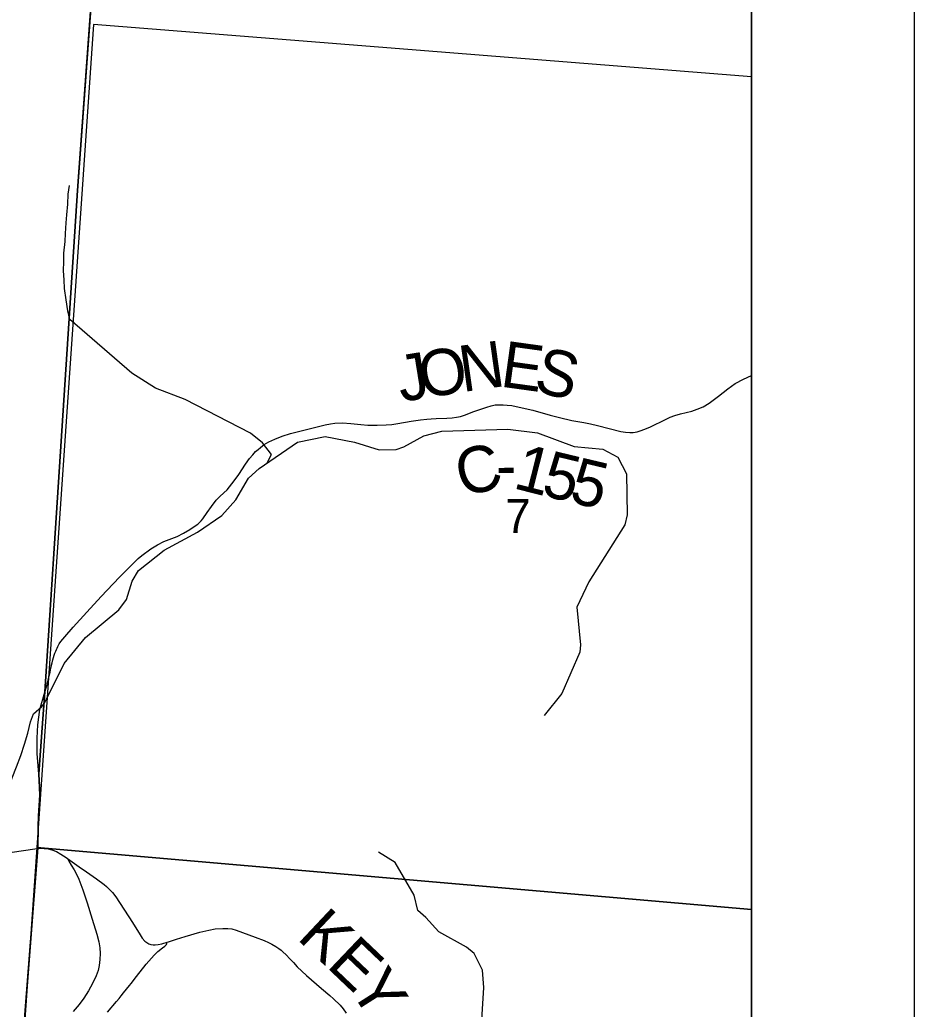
# Model space of a CAD drawing. Extents: x 0 to 42, y 0 to 22.
# Drawn here: x 8.45 to 9, y 18.928 to 19.536 of the extents above; entities that cross this region are included whole.
import ezdxf

# ---------------------------------------------------------------- set-up
doc = ezdxf.new("R2010")
doc.units = 0
for name, color, linetype in [('GM_X_County_Road', 7, 'Continuous'), ('GM_X_County_Road_Text', 7, 'Continuous'), ('GM_X_Minor_River', 7, 'Continuous'), ('GM_X_Section_Text', 7, 'Continuous'), ('GM_X_Township', 7, 'Continuous'), ('GM_X_Township_Road', 7, 'Continuous'), ('GM_X_Unincorporated', 7, 'Continuous'), ('SH_Cut_Line', 7, 'Continuous'), ('SH_Data', 7, 'Continuous')]:
    doc.layers.add(name, color=color, linetype=linetype)

msp = doc.modelspace()

# ---------------------------------------------------------------- linework, layer by layer
at = {"layer": 'GM_X_County_Road'}
for points in [[(8.46528, 19.12263), (8.46663, 19.12748), (8.46798, 19.13277), (8.46844, 19.13497), (8.46903, 19.13775), (8.46976, 19.14081), (8.47023, 19.14271), (8.47061, 19.1441), (8.47102, 19.14549), (8.47149, 19.14679), (8.47194, 19.14792), (8.47238, 19.14897), (8.47279, 19.14985), (8.47331, 19.15089), (8.47413, 19.1524), (8.4751, 19.15389), (8.47761, 19.15684), (8.48271, 19.16262), (8.49117, 19.17183), (8.4999, 19.18152), (8.50353, 19.18538), (8.51114, 19.1934), (8.51525, 19.19755), (8.51948, 19.20165), (8.52275, 19.20496), (8.52494, 19.20688), (8.53036, 19.2109), (8.53459, 19.21341), (8.53849, 19.21537), (8.54659, 19.2184), (8.55058, 19.22047), (8.55448, 19.22282), (8.55775, 19.22498), (8.55931, 19.22613), (8.56039, 19.22709), (8.56146, 19.22821), (8.56246, 19.2294), (8.56513, 19.23319), (8.56776, 19.23698), (8.57071, 19.24077), (8.57287, 19.24304), (8.57542, 19.24535), (8.57737, 19.24723), (8.58168, 19.25265), (8.58459, 19.25664), (8.58865, 19.26293), (8.5912, 19.26645), (8.59312, 19.2688), (8.59483, 19.27067), (8.59643, 19.27207), (8.59786, 19.2733), (8.6001, 19.27498), (8.60313, 19.27673), (8.60663, 19.27844), (8.61118, 19.28024), (8.61644, 19.28183), (8.63108, 19.28562), (8.63777, 19.28718), (8.64092, 19.28778), (8.64371, 19.28812), (8.64833, 19.28833), (8.6534, 19.28805), (8.65958, 19.28738), (8.66397, 19.28702), (8.66963, 19.28694), (8.67517, 19.2871), (8.67864, 19.28746), (8.68243, 19.28802), (8.69052, 19.28937), (8.69627, 19.29025), (8.70017, 19.29073), (8.70296, 19.29096), (8.70588, 19.29109), (8.71247, 19.29135), (8.71579, 19.29157), (8.71843, 19.29184), (8.72095, 19.29228), (8.72402, 19.29328), (8.72844, 19.29507), (8.73339, 19.2969), (8.73705, 19.2981), (8.73981, 19.29886), (8.74232, 19.29942), (8.74475, 19.29954), (8.74722, 19.29954), (8.74961, 19.29934), (8.75244, 19.29898), (8.7552, 19.29846), (8.76532, 19.29619), (8.77601, 19.29316), (8.78191, 19.2916), (8.78937, 19.28984), (8.7967, 19.28853), (8.80097, 19.28771), (8.80523, 19.28666), (8.81959, 19.28303), (8.82246, 19.28263), (8.82509, 19.28239), (8.82704, 19.28247), (8.82844, 19.28259), (8.82963, 19.28283), (8.83139, 19.28339), (8.83426, 19.28442), (8.83777, 19.2859), (8.84694, 19.29045), (8.84985, 19.29184), (8.85284, 19.29292), (8.85619, 19.29396), (8.86317, 19.29563), (8.86656, 19.29675), (8.8701, 19.29818), (8.87389, 19.30042), (8.87957, 19.30472), (8.88526, 19.30938), (8.88988, 19.31254), (8.89498, 19.31521), (8.9, 19.3175)], [(8.46096, 19.02669), (8.46128, 19.03985), (8.4615, 19.04636), (8.4622, 19.05908), (8.46218, 19.06373), (8.46163, 19.07227)], [(8.43815, 19.02336), (8.45911, 19.02642), (8.46096, 19.02669)], [(8.46096, 19.02669), (8.46322, 19.02669), (8.46477, 19.02662), (8.46733, 19.02626), (8.46952, 19.0257), (8.47236, 19.02465), (8.47502, 19.02314), (8.47831, 19.02094), (8.47911, 19.02037), (8.48635, 19.01523), (8.49092, 19.01212), (8.49699, 19.00795), (8.5017, 19.0045), (8.50322, 19.0032), (8.50472, 19.00182), (8.50686, 18.9995), (8.50888, 18.99685), (8.51923, 18.9811), (8.52385, 18.9735), (8.52518, 18.97136), (8.52674, 18.96951), (8.52801, 18.96864), (8.52923, 18.96801), (8.5305, 18.96754), (8.53183, 18.96731), (8.53316, 18.96731), (8.53501, 18.96754), (8.5372, 18.96801), (8.5406, 18.969), (8.54136, 18.96922), (8.54616, 18.97072), (8.55153, 18.97252), (8.56069, 18.9751), (8.56604, 18.97639), (8.57008, 18.97708), (8.57477, 18.97737), (8.57783, 18.97743), (8.58032, 18.97708), (8.58286, 18.97639), (8.59465, 18.97205), (8.6002, 18.96986), (8.60285, 18.96864), (8.60483, 18.96765), (8.60725, 18.96627), (8.60909, 18.96506), (8.61054, 18.96396), (8.61172, 18.96291), (8.61372, 18.96113), (8.61597, 18.95876), (8.61817, 18.95633), (8.62048, 18.95379), (8.62331, 18.95113), (8.62626, 18.94853), (8.63533, 18.94033), (8.64054, 18.93605), (8.64285, 18.93402), (8.64683, 18.93015), (8.64874, 18.9279), (8.6507, 18.9253)]]:
    msp.add_lwpolyline(points, dxfattribs=at)
at = {"layer": 'GM_X_Minor_River'}
for points in [[(8.48061, 19.35197), (8.47947, 19.35733), (8.47836, 19.36397), (8.47743, 19.37099), (8.47707, 19.3763), (8.47671, 19.38198), (8.47692, 19.38767), (8.47693, 19.39279), (8.47771, 19.39999), (8.47792, 19.40492), (8.47832, 19.41136), (8.47871, 19.41629), (8.4793, 19.42292), (8.4797, 19.42898), (8.48047, 19.43448)], [(8.60206, 19.2637), (8.60476, 19.26899), (8.59916, 19.27608), (8.59183, 19.28205), (8.55164, 19.30267), (8.53331, 19.30973), (8.5188, 19.31902), (8.48061, 19.35197)], [(8.46515, 19.11605), (8.47705, 19.14032), (8.49027, 19.15628), (8.51068, 19.17338), (8.51541, 19.17965), (8.51899, 19.19104), (8.52295, 19.19749), (8.53864, 19.21004), (8.55906, 19.22108), (8.57418, 19.23135), (8.58268, 19.24104), (8.59043, 19.25433), (8.59704, 19.26023), (8.62067, 19.27658), (8.63769, 19.28003), (8.65567, 19.27646), (8.67081, 19.27175), (8.6814, 19.27196), (8.68613, 19.27367), (8.69842, 19.28033), (8.70939, 19.2832), (8.75006, 19.28441), (8.76823, 19.28217), (8.79075, 19.27387), (8.80854, 19.2722), (8.81762, 19.26728), (8.82312, 19.25705), (8.82334, 19.23183), (8.82202, 19.22557), (8.79993, 19.19063), (8.79257, 19.17506), (8.79467, 19.15193), (8.7943, 19.14737), (8.78317, 19.12194), (8.7724, 19.10845)], [(8.42381, 18.98866), (8.4272, 18.98918), (8.43346, 18.99106), (8.43613, 18.99807), (8.43653, 19.00413), (8.43541, 19.00925), (8.43202, 19.01533), (8.43015, 19.02197), (8.43092, 19.02841), (8.43473, 19.03503), (8.43721, 19.04185), (8.43818, 19.04734), (8.43933, 19.05246), (8.44086, 19.05814), (8.44296, 19.06325), (8.44525, 19.07007), (8.44792, 19.07689), (8.4504, 19.0837), (8.4527, 19.09071), (8.4548, 19.09753), (8.45653, 19.10454), (8.45825, 19.10946), (8.46337, 19.11381), (8.46515, 19.11605)], [(8.74207, 18.82694), (8.73315, 18.85423), (8.72649, 18.88646), (8.72724, 18.89159), (8.73309, 18.90468), (8.73532, 18.9411), (8.73455, 18.95172), (8.72924, 18.96195), (8.7247, 18.96593), (8.70766, 18.97519), (8.6997, 18.98409), (8.69478, 18.98844), (8.6925, 18.99792), (8.68075, 19.018), (8.67052, 19.02424)]]:
    msp.add_lwpolyline(points, dxfattribs=at)
at = {"layer": 'GM_X_Township'}
msp.add_lwpolyline([(8.5294, 20.03351), (8.48531, 19.43126), (8.46517, 19.12289), (8.46366, 19.1008), (8.46152, 19.07253), (8.46207, 19.06399), (8.4621, 19.05934), (8.4614, 19.04662), (8.46117, 19.04011), (8.46085, 19.02695), (8.42127, 18.51405), (8.38769, 18.10646)], dxfattribs=at)
at = {"layer": 'GM_X_Township_Road'}
msp.add_lwpolyline([(8.9, 16.95771), (8.9, 20.00639), (8.75955, 20.01746), (8.65628, 20.02413), (8.5294, 20.03351), (8.48531, 19.43126), (8.46517, 19.12289), (8.46366, 19.1008), (8.46152, 19.07253), (8.46207, 19.06399), (8.4621, 19.05934), (8.4614, 19.04662), (8.46117, 19.04011), (8.46085, 19.02695), (8.42127, 18.51405), (8.38769, 18.10646), (8.32232, 17.47301), (8.30468, 17.09885), (8.29856, 17.02621), (8.2967, 17.00562), (8.30518, 17.00518), (8.669, 16.9761)], close=True, dxfattribs=at)
for points in [[(8.46163, 19.07227), (8.46064, 19.08501), (8.46049, 19.09451), (8.46093, 19.10253), (8.46227, 19.11204), (8.46528, 19.12263)], [(8.46096, 19.02669), (8.46128, 19.03985), (8.4615, 19.04636), (8.4622, 19.05908), (8.46218, 19.06373), (8.46163, 19.07227)], [(8.47911, 19.02037), (8.4801, 19.01869), (8.48149, 19.01632), (8.48328, 19.01349), (8.48496, 19.01043), (8.48624, 19.00759), (8.48868, 19.0012), (8.4913, 18.99323), (8.49444, 18.98314), (8.49726, 18.97394), (8.49847, 18.96912), (8.49908, 18.96544), (8.4993, 18.96203), (8.49917, 18.95831), (8.4987, 18.95461), (8.49802, 18.95159), (8.49675, 18.94813), (8.49461, 18.9435), (8.49218, 18.93905), (8.48929, 18.93449), (8.48629, 18.9305), (8.48276, 18.92628)], [(8.50371, 18.92578), (8.50937, 18.93234), (8.51095, 18.93424), (8.5123, 18.93594), (8.5136, 18.93768), (8.51734, 18.94222), (8.51827, 18.94345), (8.52169, 18.94786), (8.52764, 18.95542), (8.53256, 18.96101), (8.53479, 18.96315), (8.5377, 18.96546), (8.53908, 18.96657), (8.53958, 18.96703), (8.54008, 18.9676), (8.54036, 18.96815), (8.5406, 18.969)]]:
    msp.add_lwpolyline(points, dxfattribs=at)
at = {"layer": 'GM_X_Unincorporated'}
for points in [[(8.9, 18.98896), (8.9, 19.50128), (8.49509, 19.53339), (8.4604, 19.02708)], [(8.9, 18.47928), (8.9, 18.98896), (8.4604, 19.02708), (8.4249, 18.52131), (8.42464, 18.51753)]]:
    msp.add_lwpolyline(points, close=True, dxfattribs=at)
at = {"layer": 'SH_Cut_Line'}
for points in [[(8.17227, 15.49063), (8.24231, 16.32059), (8.26133, 16.54947), (8.2967, 17.00562), (8.29856, 17.02621), (8.30468, 17.09885), (8.32232, 17.47301), (8.38769, 18.10646), (8.42127, 18.51405), (8.46085, 19.02695), (8.46117, 19.04011), (8.4614, 19.04662), (8.4621, 19.05934), (8.46207, 19.06399), (8.46152, 19.07253), (8.46366, 19.1008), (8.46517, 19.12289), (8.48531, 19.43126), (8.5294, 20.03351), (8.55155, 20.24789), (8.57059, 20.47391), (8.6039, 20.89865), (8.604, 20.9), (2.1, 20.9)], [(8.9, 14.1), (8.9, 20.00639), (8.75955, 20.01746), (8.65628, 20.02413), (8.5294, 20.03351), (8.48531, 19.43126), (8.46517, 19.12289), (8.46366, 19.1008), (8.46152, 19.07253), (8.46207, 19.06399), (8.4621, 19.05934), (8.4614, 19.04662), (8.46117, 19.04011), (8.46085, 19.02695), (8.42127, 18.51405), (8.38769, 18.10646), (8.32232, 17.47301), (8.30468, 17.09885), (8.29856, 17.02621), (8.2967, 17.00562), (8.26133, 16.54947), (8.24231, 16.32059), (8.17227, 15.49063)]]:
    msp.add_lwpolyline(points, dxfattribs=at)
at = {"layer": 'SH_Data'}
for p, q in [((9, 21), (9, 14)), ((8.9, 20.9), (8.9, 14.1))]:
    msp.add_line(p, q, dxfattribs=at)

# ---------------------------------------------------------------- texts
at = {"layer": 'GM_X_County_Road_Text'}
for s, rotation, p in [('N', 8.08451, (8.7221, 19.30728)), ('E', 352.13688, (8.74477, 19.31079)), ('J', 9.20574, (8.68441, 19.30118)), ('O', 9.18984, (8.69757, 19.30331)), ('S', 346.32389, (8.76507, 19.30803)), ('C', 14.32827, (8.72199, 19.24259)), ('1', 345.80977, (8.75256, 19.24837)), ('5', 346.408, (8.76984, 19.244)), ('5', 346.65848, (8.78699, 19.23986)), ('-', 0.04684, (8.74275, 19.24813)), ('K', 316.75443, (8.61969, 18.9712)), ('E', 316.41684, (8.63786, 18.95411)), ('Y', 302.45988, (8.6521, 18.94086))]:
    msp.add_text(s, height=0.02841, rotation=rotation, dxfattribs=at).set_placement(p)
at = {"layer": 'GM_X_Section_Text'}
msp.add_text('7', height=0.02093, rotation=0.00001, dxfattribs=at).set_placement((8.74848, 19.22064))

doc.saveas('drawing.dxf')
